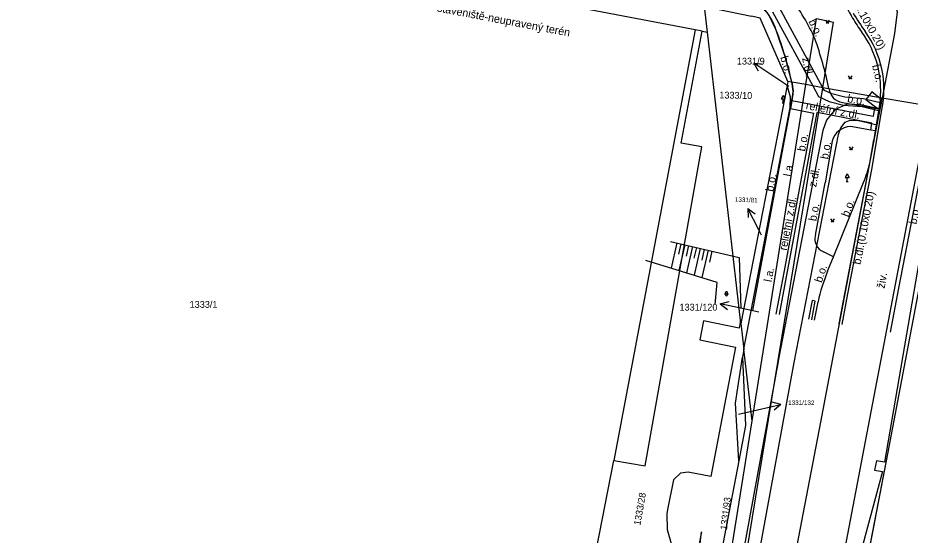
# Model space of a CAD drawing. Extents: x -601602 to -600882, y -1162594 to -1161950.
# Drawn here: x -601431.1 to -601319.6, y -1162401 to -1162336.4 of the extents above; entities that cross this region are included whole.
import ezdxf

# ---------------------------------------------------------------- set-up
doc = ezdxf.new("R2010")
doc.units = 0
for name, color, linetype in [('KN_Hranice parcel', 7, 'Continuous'), ('KN_Parcelní čísla', 7, 'Continuous'), ('KN_Pop  PČ popisy', 7, 'Continuous'), ('KN_Vnitřní kresba', 7, 'Continuous'), ('KN_Věcná břemena k části', 7, 'Continuous'), ('Vrstva 13', 7, 'Continuous'), ('Vrstva 14', 7, 'Continuous'), ('Vrstva 16', 7, 'Continuous'), ('VRSTVA 3', 7, 'Continuous'), ('Vrstva 8', 7, 'Continuous')]:
    doc.layers.add(name, color=color, linetype=linetype)

# ---------------------------------------------------------------- blocks, each defined once
blk = doc.blocks.new('1029_25')
at = {"layer": 'KN_Pop  PČ popisy'}
for p, q in [((-2.94, 0.62), (-1.85, 0.91)), ((0, 0), (-2.94, 0.62)), ((-2.94, 0.62), (-2.06, -0.07))]:
    blk.add_line(p, q, dxfattribs=at)
blk = doc.blocks.new('1029_24')
at = {"layer": 'KN_Pop  PČ popisy'}
for p, q in [((0, 0), (-1.36, 2.67)), ((-1.36, 2.67), (-0.46, 2.01)), ((-1.36, 2.67), (-1.35, 1.55))]:
    blk.add_line(p, q, dxfattribs=at)
blk = doc.blocks.new('1029_59')
at = {"layer": 'KN_Pop  PČ popisy'}
for p, q in [((0, 0), (2.92, 0.68)), ((2.92, 0.68), (1.84, 0.94)), ((2.92, 0.68), (2.06, -0.04))]:
    blk.add_line(p, q, dxfattribs=at)
blk = doc.blocks.new('1029_64')
at = {"layer": 'KN_Pop  PČ popisy'}
for p, q in [((0, 0), (-2.49, 1.68)), ((-2.49, 1.68), (-1.38, 1.53)), ((-2.49, 1.68), (-1.94, 0.7))]:
    blk.add_line(p, q, dxfattribs=at)

msp = doc.modelspace()

# ---------------------------------------------------------------- linework, layer by layer
at = {"layer": 'KN_Hranice parcel'}
for p, q in [((-601345.55, -1162338.03), (-601344.9, -1162338.15)), ((-601340.77, -1162374.15), (-601344.9, -1162338.15)), ((-601321.53, -1162338.33), (-601323.06, -1162346.39)), ((-601339.33, -1162386.71), (-601332.62, -1162344.71)), ((-601334.86, -1162344.32), (-601334.96, -1162344.82)), ((-601334.38, -1162344.4), (-601334.86, -1162344.32)), ((-601332.62, -1162344.71), (-601334.38, -1162344.4)), ((-601334.96, -1162344.82), (-601340.72, -1162374.58)), ((-601330.72, -1162386.88), (-601323.06, -1162346.39)), ((-601317.17, -1162347.42), (-601323.06, -1162346.39)), ((-601340.35, -1162377.78), (-601334.58, -1162347.56)), ((-601340.72, -1162374.58), (-601340.77, -1162374.15)), ((-601340.72, -1162374.58), (-601340.35, -1162377.78)), ((-601340.35, -1162377.78), (-601340.54, -1162378.75)), ((-601339.33, -1162386.71), (-601340.35, -1162377.78))]:
    msp.add_line(p, q, dxfattribs=at)
for points in [[(-601345.55, -1162338.03), (-601346.43, -1162337.86), (-601465.12, -1162315.27)], [(-601325.05, -1162328.21), (-601322.32, -1162331.64), (-601321.22, -1162335.6), (-601321.53, -1162338.33)], [(-601334.38, -1162344.4), (-601335.15, -1162341.34), (-601336.31, -1162337.92), (-601337.24, -1162335.98), (-601338.79, -1162334.26), (-601340.6, -1162333.12), (-601340.99, -1162333.19)], [(-601344.9, -1162338.15), (-601345.27, -1162334.93), (-601339.42, -1162336.16)], [(-601334.86, -1162344.32), (-601338.32, -1162336.39), (-601339.42, -1162336.16)], [(-601367.02, -1162467.69), (-601361.71, -1162440.07), (-601354.78, -1162403.52), (-601358.76, -1162402.75), (-601356.61, -1162391.67), (-601352.68, -1162392.37), (-601345.61, -1162352.5), (-601348.18, -1162352.04), (-601345.55, -1162338.03)], [(-601334.38, -1162344.4), (-601334.33, -1162344.62), (-601334.21, -1162345.52), (-601334.58, -1162347.56)], [(-601323.06, -1162346.39), (-601330.48, -1162345.09), (-601332.62, -1162344.71)], [(-601334.58, -1162347.56), (-601334.51, -1162346.29), (-601334.96, -1162344.82)], [(-601342.45, -1162480.03), (-601331.27, -1162421.43), (-601325.33, -1162390.2), (-601319.3, -1162358.55), (-601317.17, -1162347.42)], [(-601341.27, -1162489.73), (-601339.53, -1162480.59), (-601328.28, -1162421.68), (-601322.37, -1162390.85), (-601316.38, -1162359.28), (-601314.18, -1162347.94)], [(-601340.77, -1162374.15), (-601340.96, -1162375.15), (-601345.4, -1162374.23), (-601345.87, -1162376.6), (-601341.42, -1162377.52), (-601344.5, -1162393.69), (-601347.31, -1162393.13), (-601348.27, -1162393.25), (-601349.14, -1162394.09), (-601349.9, -1162397.8), (-601349.97, -1162398.34), (-601349.96, -1162400.31), (-601349.28, -1162402.65), (-601347.05, -1162405.28), (-601346.6, -1162405.5)], [(-601340.98, -1162391.72), (-601341.41, -1162384.5), (-601340.54, -1162378.75)], [(-601340.54, -1162378.75), (-601340.14, -1162387.32), (-601340.98, -1162391.72)], [(-601355.93, -1162486.87), (-601352.32, -1162468.05), (-601339.33, -1162386.71)], [(-601350.04, -1162488.07), (-601349.42, -1162484.81), (-601340.01, -1162435.29), (-601330.72, -1162386.88)], [(-601340.98, -1162391.72), (-601343.76, -1162406.27), (-601345.2, -1162404.42), (-601345.63, -1162403.27), (-601345.82, -1162402.05), (-601345.67, -1162400.61), (-601346.6, -1162405.5)]]:
    msp.add_lwpolyline(points, dxfattribs=at)
at = {"layer": 'KN_Pop  PČ popisy'}
for p, q in [((-601334.73, -1162344.96), (-601336.62, -1162343.69)), ((-601338.16, -1162363.52), (-601338.49, -1162362.87)), ((-601338.5, -1162373.13), (-601340.36, -1162372.73)), ((-601341.01, -1162385.91), (-601338.65, -1162385.35))]:
    msp.add_line(p, q, dxfattribs=at)
at = {"layer": 'KN_Vnitřní kresba'}
for p, q in [((-601331.51, -1162337.76), (-601331.3, -1162336.45)), ((-601331.3, -1162336.45), (-601329.14, -1162336.92)), ((-601330.48, -1162345.09), (-601329.14, -1162336.92)), ((-601346.43, -1162337.86), (-601356.61, -1162391.67)), ((-601332.62, -1162344.71), (-601331.51, -1162337.76)), ((-601345.13, -1162434.46), (-601330.48, -1162345.09))]:
    msp.add_line(p, q, dxfattribs=at)
at = {"layer": 'KN_Věcná břemena k části'}
for points in [[(-601336.76, -1162335.6), (-601331.74, -1162344.87), (-601331.02, -1162346.2), (-601329.72, -1162346.81), (-601327.89, -1162347.26), (-601325.56, -1162347.46), (-601323.36, -1162348), (-601323.18, -1162347.01), (-601325.4, -1162346.47), (-601327.73, -1162346.27), (-601329.38, -1162345.86), (-601330.3, -1162345.44), (-601330.48, -1162345.09), (-601335.94, -1162335.01)], [(-601316.17, -1162353.35), (-601322.79, -1162391.91), (-601323.8, -1162391.72), (-601324.02, -1162392.9), (-601323.05, -1162393.08), (-601325.79, -1162403.27)], [(-601324.94, -1162404.24), (-601322.37, -1162390.85), (-601316.38, -1162359.28)]]:
    msp.add_lwpolyline(points, dxfattribs=at)
for points in [[(-601323.08, -1162346.5), (-601323.28, -1162346.47), (-601323.48, -1162346.32), (-601324.37, -1162345.62), (-601324.74, -1162346.1), (-601325.11, -1162346.58), (-601323.76, -1162347.61), (-601323.3, -1162347.67)], [(-601323.69, -1162349.72), (-601323.32, -1162347.76), (-601325.76, -1162347.22), (-601327.47, -1162347.13), (-601328.94, -1162347.8), (-601330.04, -1162349.14), (-601330.48, -1162350.43), (-601336.04, -1162379.04), (-601336.09, -1162379.32), (-601340.48, -1162403.38), (-601349.56, -1162450.77), (-601352.32, -1162468.05), (-601355.32, -1162483.69), (-601355.93, -1162486.87), (-601354.54, -1162487.19), (-601352.24, -1162475.36), (-601348.67, -1162456.75), (-601338.52, -1162403.75), (-601334.08, -1162379.42), (-601328.54, -1162350.95), (-601328.26, -1162350.12), (-601327.68, -1162349.42), (-601327.09, -1162349.15), (-601326.02, -1162349.2)]]:
    msp.add_lwpolyline(points, close=True, dxfattribs=at)
at = {"layer": 'Vrstva 13'}
for p, q in [((-601334.22, -1162345.9), (-601334.38, -1162346.74)), ((-601334.38, -1162346.74), (-601334.55, -1162347.71)), ((-601324.21, -1162348.68), (-601334.38, -1162346.74)), ((-601328.05, -1162346.94), (-601324.03, -1162347.63)), ((-601323.33, -1162346.62), (-601323.49, -1162347.72)), ((-601336.07, -1162355.88), (-601334.55, -1162347.71)), ((-601334.55, -1162347.71), (-601331.61, -1162348.27)), ((-601324.38, -1162355.32), (-601323.1, -1162347.84)), ((-601324.03, -1162347.63), (-601324.21, -1162348.68)), ((-601324.03, -1162347.63), (-601323.49, -1162347.72)), ((-601323.49, -1162347.72), (-601323.97, -1162350.49)), ((-601333.14, -1162356.42), (-601331.61, -1162348.27)), ((-601332.73, -1162356.52), (-601331.18, -1162348.21)), ((-601324.36, -1162349.51), (-601331.18, -1162348.21)), ((-601324.51, -1162350.4), (-601327.05, -1162349.96)), ((-601324.51, -1162350.4), (-601324.36, -1162349.51)), ((-601323.97, -1162350.49), (-601324.51, -1162350.4)), ((-601329.31, -1162351.76), (-601330.2, -1162356.97)), ((-601324.62, -1162354.52), (-601324.13, -1162351.59)), ((-601317.67, -1162352.72), (-601321.02, -1162370.16)), ((-601327.92, -1162371.72), (-601324.62, -1162354.52)), ((-601338.21, -1162367.32), (-601336.07, -1162355.88)), ((-601327.36, -1162370.85), (-601324.38, -1162355.32)), ((-601335.3, -1162367.97), (-601333.14, -1162356.42)), ((-601334.89, -1162368.07), (-601332.73, -1162356.52)), ((-601331.42, -1162363.53), (-601330.2, -1162356.97)), ((-601329.16, -1162366.25), (-601325.4, -1162356.93)), ((-601329.16, -1162366.25), (-601330.39, -1162365.6)), ((-601329.89, -1162368.02), (-601329.16, -1162366.25)), ((-601339.25, -1162372.93), (-601338.21, -1162367.32)), ((-601336.31, -1162373.39), (-601335.3, -1162367.97)), ((-601335.9, -1162373.45), (-601334.89, -1162368.07)), ((-601321.02, -1162370.16), (-601322.08, -1162375.63)), ((-601328.09, -1162374.68), (-601327.36, -1162370.85)), ((-601331.83, -1162371.7), (-601332.28, -1162374.02)), ((-601331.87, -1162374.09), (-601331.43, -1162371.77)), ((-601331.43, -1162371.77), (-601331.83, -1162371.7)), ((-601331.53, -1162374.14), (-601331.09, -1162371.85)), ((-601328.47, -1162374.62), (-601327.92, -1162371.72))]:
    msp.add_line(p, q, dxfattribs=at)
for centre, radius, start, end in [((-601343.88, -1162340.37), 7.95, 17.9206, 65.6569), ((-601356.28, -1162350.18), 27.22, 24.3626, 36.9388), ((-601266.85, -1162301.88), 69.15, 207.4597, 209.9442), ((-601300.58, -1162320.47), 30.26, 210.3648, 215.4876), ((-601299.75, -1162319.9), 31.66, 211.4157, 215.2055), ((-601374.14, -1162352.74), 40.63, 11.5319, 21.3953), ((-601335.34, -1162345.36), 12.49, 348.5356, 35.8774), ((-601381.9, -1162356.44), 53.37, 12.156, 19.1285), ((-601335.36, -1162345.33), 12.1, 353.8687, 36.3895), ((-601338.27, -1162345.6), 4.06, 355.8097, 14.0139), ((-601327.75, -1162344.97), 1.99, 186.5882, 261.4016), ((-601327.03, -1162352.31), 2.35, 90.5454, 166.5264), ((-601252.53, -1162361.44), 72.27, 171.2835, 172.1647), ((-601341.85, -1162350.27), 17.75, 337.974, 346.1575), ((-601329.76, -1162364), 1.72, 164.3493, 248.5591), ((-601311.69, -1162375.83), 19.8, 156.7876, 168.4192)]:
    msp.add_arc(centre, radius, start, end, dxfattribs=at)
at = {"layer": 'Vrstva 14'}
for p, q in [((-601349.51, -1162364.31), (-601340.94, -1162366.3)), ((-601348.72, -1162364.49), (-601349.46, -1162367.65)), ((-601348.24, -1162364.6), (-601348.53, -1162365.88)), ((-601347.75, -1162364.72), (-601348.5, -1162367.94)), ((-601347.26, -1162364.83), (-601347.57, -1162366.14)), ((-601346.78, -1162364.95), (-601347.54, -1162368.24)), ((-601346.29, -1162365.06), (-601346.6, -1162366.39)), ((-601345.8, -1162365.17), (-601346.58, -1162368.53)), ((-601345.32, -1162365.28), (-601345.63, -1162366.64)), ((-601344.83, -1162365.4), (-601345.63, -1162368.83)), ((-601344.34, -1162365.51), (-601344.66, -1162366.9)), ((-601343.71, -1162369.42), (-601352.62, -1162366.67)), ((-601340.94, -1162366.3), (-601340.73, -1162372.7)), ((-601343.93, -1162372.19), (-601343.71, -1162369.42)), ((-601342.79, -1162370.84), (-601342.29, -1162370.84)), ((-601342.66, -1162370.96), (-601342.66, -1162370.71)), ((-601342.41, -1162370.96), (-601342.41, -1162370.71))]:
    msp.add_line(p, q, dxfattribs=at)
for centre, start, end in [((-601342.54, -1162370.71), 0, 180), ((-601342.54, -1162370.96), 180, 360)]:
    msp.add_arc(centre, 0.125, start, end, dxfattribs=at)
at = {"layer": 'VRSTVA 3'}
for points in [[(-601330.15, -1162336.66), (-601329.9, -1162337.03), (-601329.65, -1162336.66)], [(-601327.32, -1162343.61), (-601327.07, -1162343.98), (-601326.82, -1162343.61)], [(-601327.22, -1162352.5), (-601326.97, -1162352.87), (-601326.72, -1162352.5)], [(-601329.54, -1162361.47), (-601329.29, -1162361.84), (-601329.04, -1162361.47)]]:
    msp.add_lwpolyline(points, dxfattribs=at)
for centre in [(-601330.03, -1162337.01), (-601329.78, -1162337.01), (-601327.19, -1162343.96), (-601326.94, -1162343.96), (-601327.09, -1162352.85), (-601326.84, -1162352.85), (-601329.41, -1162361.82), (-601329.16, -1162361.82)]:
    msp.add_circle(centre, 0.025, dxfattribs=at)
at = {"layer": 'Vrstva 8'}
for p, q in [((-601335.43, -1162346.07), (-601335.68, -1162346.5)), ((-601335.68, -1162346.5), (-601335.18, -1162346.5)), ((-601335.56, -1162347), (-601335.31, -1162347)), ((-601335.43, -1162346.07), (-601335.18, -1162346.5)), ((-601335.43, -1162347), (-601335.43, -1162346.5)), ((-601327.45, -1162355.87), (-601327.7, -1162356.3)), ((-601327.45, -1162355.87), (-601327.2, -1162356.3)), ((-601327.7, -1162356.3), (-601327.2, -1162356.3)), ((-601327.58, -1162356.8), (-601327.33, -1162356.8)), ((-601327.45, -1162356.8), (-601327.45, -1162356.3))]:
    msp.add_line(p, q, dxfattribs=at)

# ---------------------------------------------------------------- block references
at = {"layer": 'KN_Pop  PČ popisy'}
for name, p in [('1029_64', (-601336.62, -1162343.69)), ('1029_24', (-601338.49, -1162362.87)), ('1029_25', (-601340.36, -1162372.73)), ('1029_59', (-601338.65, -1162385.35))]:
    msp.add_blockref(name, p, dxfattribs=at)

# ---------------------------------------------------------------- texts
at = {"layer": 'KN_Parcelní čísla'}
for s, height, p in [('1331/9', 0.85, (-601341.23, -1162342.2)), ('1333/1', 0.85, (-601409.61, -1162372.6)), ('1331/120', 0.85, (-601348.4, -1162372.95)), ('1331/132', 0.569, (-601334.82, -1162384.74))]:
    msp.add_text(s, height=height, dxfattribs=at).set_placement(p)
for s, height, rotation, p in [('1333/10', 0.85, 359, (-601343.43, -1162346.43)), ('1331/81', 0.569, 358, (-601341.49, -1162359.34)), ('1333/28', 0.85, 80, (-601353.29, -1162399.83)), ('1331/93', 0.85, 83, (-601342.47, -1162400.4))]:
    msp.add_text(s, height=height, rotation=rotation, dxfattribs=at).set_placement(p)
at = {"layer": 'Vrstva 16'}
for s, rotation, p in [('b.dl.(0.10x0.20)', 299.5619, (-601328.01, -1162332.37)), ('staveniště-neupravený terén', 349.2216, (-601378.74, -1162335.55)), ('b.o.', 295.8108, (-601332.31, -1162336.81)), ('b.o.', 285.962, (-601335.83, -1162341.29)), ('z.dl.', 281.8841, (-601333.09, -1162341.41)), ('b.o.', 283.6393, (-601324.36, -1162342.33)), ('b.o.', 349.7092, (-601327.49, -1162346.89)), ('reliéfní z.dl.', 349.2002, (-601332.67, -1162347.75)), ('b.o.', 79.4527, (-601332.72, -1162353.11)), ('b.o.', 79.4527, (-601329.84, -1162354.09)), ('l.a.', 79.4608, (-601334.45, -1162356.25)), ('z.dl.', 79.4345, (-601331.32, -1162357.56)), ('b.o.', 79.4527, (-601336.68, -1162358.14)), ('b.dl.(0.10x0.20)', 79.1338, (-601325.78, -1162367.26)), ('reliéfní z.dl.', 79.4073, (-601335.01, -1162365.49)), ('b.o.', 79.4527, (-601331.31, -1162361.83)), ('b.o.', 69.3548, (-601327.29, -1162361.33)), ('b.o.', 78.6871, (-601318.8, -1162362.22)), ('l.a.', 79.4488, (-601336.9, -1162369.43)), ('b.o.', 71.9196, (-601330.62, -1162369.53)), ('živ.', 80.0812, (-601322.78, -1162370.24))]:
    msp.add_text(s, height=1, rotation=rotation, dxfattribs=at).set_placement(p)

doc.saveas('drawing.dxf')
